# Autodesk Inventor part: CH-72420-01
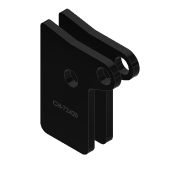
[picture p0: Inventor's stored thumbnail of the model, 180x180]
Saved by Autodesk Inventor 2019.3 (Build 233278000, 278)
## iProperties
Created: 2013-06
Part Number: CH-72420-01
Material: Ogólny
Document SubType Name: Modeling
Designer: CADENGINEERING4
Density: 1 g/cm^3
Appearance: Gładki — czarny
Author: CADENGINEERING4
Revision Number: ÈÎºÎ
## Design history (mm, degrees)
feature "¾µÏò1"
feature "ÇÐ³ý-À­Éì1"
node "Bryła1"
node "Bryła22"
node "Bryła23"
